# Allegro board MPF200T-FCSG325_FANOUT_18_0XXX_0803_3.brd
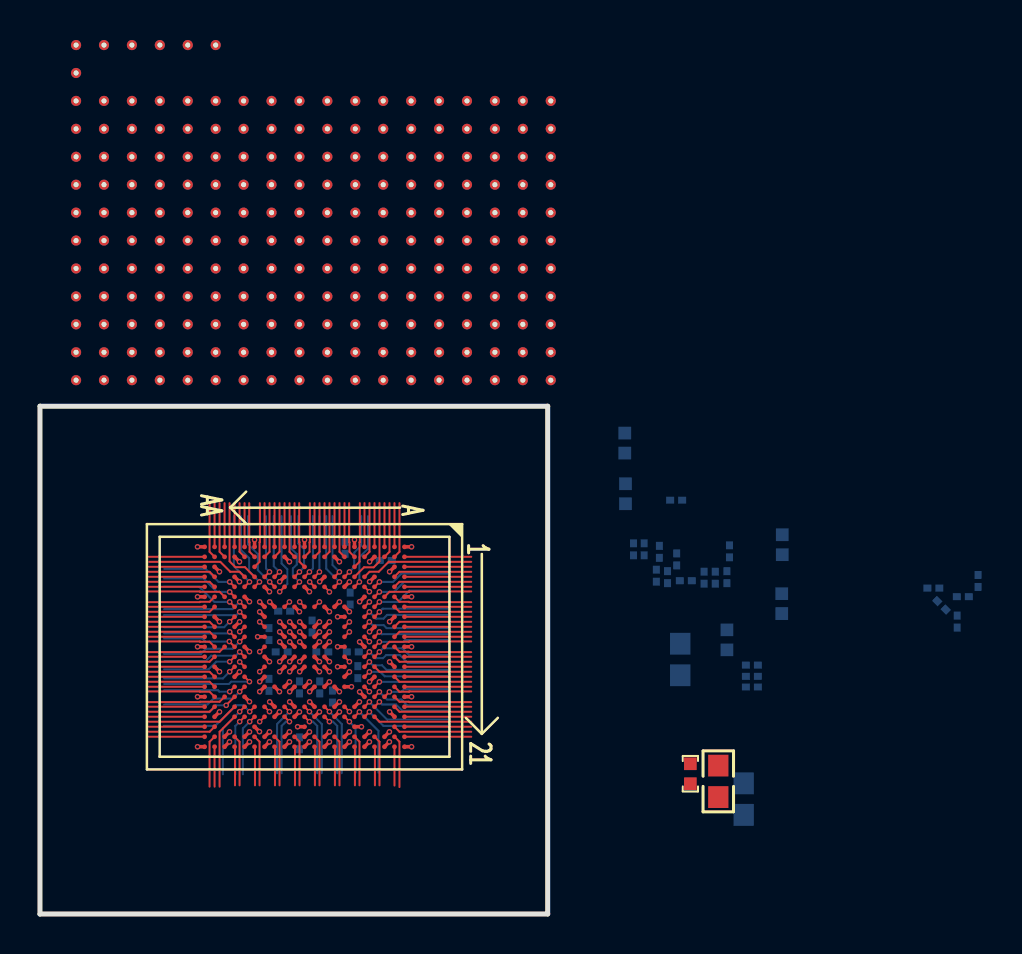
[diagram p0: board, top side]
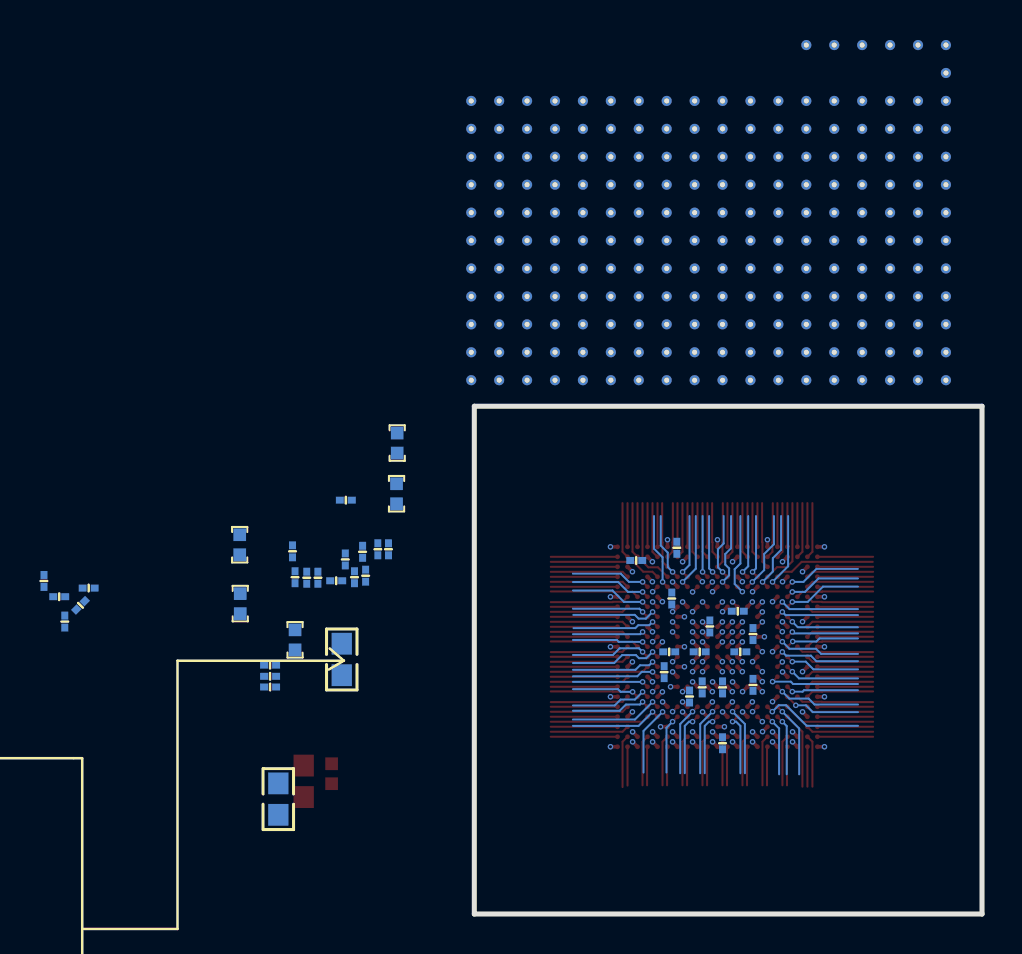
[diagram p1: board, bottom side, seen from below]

Outline 25.4 x 25.4 mm; copper layers: TOP, L2_GND1, L3_SIG1, L4_PWR, L5_GND2, BOTTOM. Coordinates in mm from the lower left corner of the outline.
Outline path: 0,25.4 0,0 25.4,0 25.4,25.4 0,25.4

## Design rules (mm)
net group DIFFPAIR0: nets N38034884 N38034886
net group DIFFPAIR1: nets N38034948 N38034950
net group DIFFPAIR2: nets N38034916 N38034918
net group XCVR_TX0: nets N38004278 N38004279
net group POWER: nets VDD

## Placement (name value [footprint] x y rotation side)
C33  0.01uF_16V  [BGA0201]  45.1 15.44 135 bottom
C34  0.1uF_16V  [BGA0201]  35.62 11.36 180 bottom
C36  0.1uF_16V  [BGA0201]  15.27 18.32 90 bottom
C37  0.01uF_16V  [BGA0201]  13.62 14.38 270 bottom
C38  0.1uF_16V  [BGA0201]  46.93 16.66 270 bottom
C40  0.1uF_16V  [BGA0201]  17.3 17.69 0 bottom
C41  0.1uF_16V  [BGA0201]  12.98 11.34 90 bottom
C42  0.1uF_16V  [BGA0201]  12.98 8.54 90 bottom
C45  0.1uF_16V  [BGA0201]  12.09 13.11 180 bottom
C46  0.1uF_16V  [BGA0201]  32.31 16.67 0 bottom
C49  0.1uF_16V_NL  [BGA0201]  14.63 10.88 270 bottom
C52  10uF_6.3V  [C0402]  37.11 15.53 270 bottom
C53  0.1uF_16V_NL  [BGA0201]  14 11.34 90 bottom
C55  10uF_6.3V  [C0402]  29.29 21.02 270 bottom
C56  0.1uF_16V_NL  [BGA0201]  45.89 14.63 270 bottom
C57  0.1uF_16V_NL  [BGA0201]  14.12 13.11 0 bottom
C60  4.7nF_16V  [BGA0201]  29.7 18.24 270 bottom
C62  4.7nF_16V  [BGA0201]  30.84 16.92 90 bottom
C66  4.7nF_16V  [BGA0201]  33.23 16.82 90 bottom
C71  0.01uF_16V  [BGA0201]  34.37 16.85 270 bottom
C76  0.1uF_16V  [BGA0201]  30.99 18.12 90 bottom
C78  47uF_4V  [C0603]  35.21 5.75 90 bottom
C79  0.1uF_16V  [BGA0201]  33.78 16.82 270 bottom
C80  0.1uF_16V  [BGA0201]  34.5 18.14 90 bottom
C82  0.1uF_16V  [BGA0201]  30.23 18.24 270 bottom
C83  0.1uF_16V  [BGA0201]  31.85 17.74 270 bottom
C84  0.1uF_16V  [BGA0201]  31.4 16.85 90 bottom
C85  10uF_6.3V  [C0402]  37.14 18.47 270 bottom
C86  0.1uF_16V  [BGA0201]  11.46 14 90 bottom
C88  0.1uF_16V  [BGA0201]  35.62 12.45 180 bottom
C95  47uF_4V  [C0603]  33.94 6.64 270 top
C96  10uF_6.3V  [C0402]  34.37 13.71 270 bottom
C103  0.1uF_16V  [BGA0201]  35.62 11.89 180 bottom
C104  0.1uF_16V  [BGA0201]  15.65 13.11 0 bottom
C105  0.1uF_16V  [BGA0201]  15.9 12.1 90 bottom
C106  0.1uF_16V  [BGA0201]  46.17 15.87 0 bottom
C107  0.1uF_16V  [BGA0201]  44.7 16.3 0 bottom
C108  0.1uF_16V  [BGA0201]  15.52 15.78 270 bottom
C110  0.1uF_16V  [BGA0201]  31.83 20.7 0 bottom
C111  0.1uF_16V  [BGA0201]  11.46 11.46 270 bottom
C112  0.1uF_16V  [BGA0201]  12.22 15.15 180 bottom
C113  10uF_6.3V  [C0402]  32.54 7.02 270 top
C115  4.7uF_10V  [C0402]  29.26 23.56 270 bottom
C1463  47uF_4V  [C0603]  32.03 12.73 90 bottom
NOREF  -  []  -0.13 3.15 0 top
NOREF#2  -  []  229.37 -121.61 0 top
TP1  -  [TP_VIA]  7.39 43.47 0 top
TP2  -  [TP_VIA]  8.79 43.47 0 top
TP16  -  [TP_VIA]  1.81 43.47 0 top
TP17  -  [TP_VIA]  3.2 43.47 0 top
TP18  -  [TP_VIA]  4.6 43.47 0 top
TP19  -  [TP_VIA]  6 43.47 0 top
TP20  -  [TP_VIA]  15.78 33.69 0 top
TP21  -  [TP_VIA]  6 35.09 0 top
TP22  -  [TP_VIA]  19.97 35.09 0 top
TP23  -  [TP_VIA]  21.36 35.09 0 top
TP24  -  [TP_VIA]  22.76 35.09 0 top
TP25  -  [TP_VIA]  24.16 35.09 0 top
TP26  -  [TP_VIA]  25.55 35.09 0 top
TP27  -  [TP_VIA]  1.81 36.48 0 top
TP28  -  [TP_VIA]  3.2 36.48 0 top
TP29  -  [TP_VIA]  4.6 36.48 0 top
TP30  -  [TP_VIA]  6 36.48 0 top
TP31  -  [TP_VIA]  7.39 36.48 0 top
TP32  -  [TP_VIA]  8.79 36.48 0 top
TP33  -  [TP_VIA]  10.19 36.48 0 top
TP34  -  [TP_VIA]  11.58 36.48 0 top
TP35  -  [TP_VIA]  12.98 36.48 0 top
TP36  -  [TP_VIA]  14.38 36.48 0 top
TP37  -  [TP_VIA]  15.78 36.48 0 top
TP38  -  [TP_VIA]  17.17 36.48 0 top
TP39  -  [TP_VIA]  18.57 36.48 0 top
TP40  -  [TP_VIA]  19.97 36.48 0 top
TP41  -  [TP_VIA]  21.36 36.48 0 top
TP42  -  [TP_VIA]  22.76 36.48 0 top
TP43  -  [TP_VIA]  24.16 36.48 0 top
TP44  -  [TP_VIA]  25.55 36.48 0 top
TP45  -  [TP_VIA]  1.81 37.88 0 top
TP46  -  [TP_VIA]  3.2 37.88 0 top
TP47  -  [TP_VIA]  4.6 37.88 0 top
TP48  -  [TP_VIA]  6 37.88 0 top
TP49  -  [TP_VIA]  7.39 37.88 0 top
TP50  -  [TP_VIA]  8.79 37.88 0 top
TP51  -  [TP_VIA]  10.19 37.88 0 top
TP52  -  [TP_VIA]  11.58 37.88 0 top
TP53  -  [TP_VIA]  12.98 37.88 0 top
TP54  -  [TP_VIA]  14.38 37.88 0 top
TP55  -  [TP_VIA]  15.78 37.88 0 top
TP56  -  [TP_VIA]  17.17 37.88 0 top
TP57  -  [TP_VIA]  18.57 37.88 0 top
TP58  -  [TP_VIA]  19.97 37.88 0 top
TP59  -  [TP_VIA]  21.36 37.88 0 top
TP60  -  [TP_VIA]  22.76 37.88 0 top
TP61  -  [TP_VIA]  24.16 37.88 0 top
TP62  -  [TP_VIA]  25.55 37.88 0 top
TP63  -  [TP_VIA]  1.81 39.28 0 top
TP64  -  [TP_VIA]  3.2 39.28 0 top
TP65  -  [TP_VIA]  4.6 39.28 0 top
TP66  -  [TP_VIA]  6 39.28 0 top
TP67  -  [TP_VIA]  7.39 39.28 0 top
TP68  -  [TP_VIA]  8.79 39.28 0 top
TP69  -  [TP_VIA]  10.19 39.28 0 top
TP70  -  [TP_VIA]  11.58 39.28 0 top
TP71  -  [TP_VIA]  12.98 39.28 0 top
TP72  -  [TP_VIA]  14.38 39.28 0 top
TP73  -  [TP_VIA]  15.78 39.28 0 top
TP74  -  [TP_VIA]  17.17 39.28 0 top
TP75  -  [TP_VIA]  18.57 39.28 0 top
TP76  -  [TP_VIA]  19.97 39.28 0 top
TP77  -  [TP_VIA]  21.36 39.28 0 top
TP78  -  [TP_VIA]  22.76 39.28 0 top
TP79  -  [TP_VIA]  24.16 39.28 0 top
TP80  -  [TP_VIA]  25.55 39.28 0 top
TP81  -  [TP_VIA]  1.81 40.67 0 top
TP82  -  [TP_VIA]  3.2 40.67 0 top
TP83  -  [TP_VIA]  4.6 40.67 0 top
TP84  -  [TP_VIA]  6 40.67 0 top
TP85  -  [TP_VIA]  7.39 40.67 0 top
TP86  -  [TP_VIA]  8.79 40.67 0 top
TP87  -  [TP_VIA]  10.19 40.67 0 top
TP88  -  [TP_VIA]  11.58 40.67 0 top
TP89  -  [TP_VIA]  12.98 40.67 0 top
TP90  -  [TP_VIA]  14.38 40.67 0 top
TP91  -  [TP_VIA]  15.78 40.67 0 top
TP92  -  [TP_VIA]  17.17 40.67 0 top
TP93  -  [TP_VIA]  18.57 40.67 0 top
TP94  -  [TP_VIA]  19.97 40.67 0 top
TP95  -  [TP_VIA]  21.36 40.67 0 top
TP96  -  [TP_VIA]  22.76 40.67 0 top
TP97  -  [TP_VIA]  24.16 40.67 0 top
TP98  -  [TP_VIA]  25.55 40.67 0 top
TP99  -  [TP_VIA]  1.81 42.07 0 top
TP100  -  [TP_VIA]  1.81 26.7 0 top
TP101  -  [TP_VIA]  3.2 26.7 0 top
TP102  -  [TP_VIA]  4.6 26.7 0 top
TP103  -  [TP_VIA]  6 26.7 0 top
TP104  -  [TP_VIA]  7.39 26.7 0 top
TP105  -  [TP_VIA]  8.79 26.7 0 top
TP106  -  [TP_VIA]  10.19 26.7 0 top
TP107  -  [TP_VIA]  11.58 26.7 0 top
TP108  -  [TP_VIA]  12.98 26.7 0 top
TP109  -  [TP_VIA]  14.38 26.7 0 top
TP110  -  [TP_VIA]  15.78 26.7 0 top
TP111  -  [TP_VIA]  17.17 26.7 0 top
TP112  -  [TP_VIA]  18.57 26.7 0 top
TP113  -  [TP_VIA]  19.97 26.7 0 top
TP114  -  [TP_VIA]  21.36 26.7 0 top
TP115  -  [TP_VIA]  22.76 26.7 0 top
TP116  -  [TP_VIA]  24.16 26.7 0 top
TP117  -  [TP_VIA]  25.55 26.7 0 top
TP118  -  [TP_VIA]  1.81 28.1 0 top
TP119  -  [TP_VIA]  3.2 28.1 0 top
TP120  -  [TP_VIA]  4.6 28.1 0 top
TP121  -  [TP_VIA]  6 28.1 0 top
TP122  -  [TP_VIA]  7.39 28.1 0 top
TP123  -  [TP_VIA]  8.79 28.1 0 top
TP124  -  [TP_VIA]  10.19 28.1 0 top
TP125  -  [TP_VIA]  11.58 28.1 0 top
TP126  -  [TP_VIA]  12.98 28.1 0 top
TP127  -  [TP_VIA]  14.38 28.1 0 top
TP128  -  [TP_VIA]  15.78 28.1 0 top
TP129  -  [TP_VIA]  17.17 28.1 0 top
TP130  -  [TP_VIA]  18.57 28.1 0 top
TP131  -  [TP_VIA]  19.97 28.1 0 top
TP132  -  [TP_VIA]  21.36 28.1 0 top
TP133  -  [TP_VIA]  22.76 28.1 0 top
TP134  -  [TP_VIA]  24.16 28.1 0 top
TP135  -  [TP_VIA]  25.55 28.1 0 top
TP136  -  [TP_VIA]  1.81 29.5 0 top
TP137  -  [TP_VIA]  3.2 29.5 0 top
TP138  -  [TP_VIA]  4.6 29.5 0 top
TP139  -  [TP_VIA]  6 29.5 0 top
TP140  -  [TP_VIA]  7.39 29.5 0 top
TP141  -  [TP_VIA]  8.79 29.5 0 top
TP142  -  [TP_VIA]  10.19 29.5 0 top
TP143  -  [TP_VIA]  11.58 29.5 0 top
TP144  -  [TP_VIA]  12.98 29.5 0 top
TP145  -  [TP_VIA]  14.38 29.5 0 top
TP146  -  [TP_VIA]  15.78 29.5 0 top
TP147  -  [TP_VIA]  17.17 29.5 0 top
TP148  -  [TP_VIA]  18.57 29.5 0 top
TP149  -  [TP_VIA]  19.97 29.5 0 top
TP150  -  [TP_VIA]  21.36 29.5 0 top
TP151  -  [TP_VIA]  22.76 29.5 0 top
TP152  -  [TP_VIA]  24.16 29.5 0 top
TP153  -  [TP_VIA]  25.55 29.5 0 top
TP154  -  [TP_VIA]  1.81 30.89 0 top
TP155  -  [TP_VIA]  3.2 30.89 0 top
TP156  -  [TP_VIA]  4.6 30.89 0 top
TP157  -  [TP_VIA]  6 30.89 0 top
TP158  -  [TP_VIA]  7.39 30.89 0 top
TP159  -  [TP_VIA]  8.79 30.89 0 top
TP160  -  [TP_VIA]  10.19 30.89 0 top
TP161  -  [TP_VIA]  11.58 30.89 0 top
TP162  -  [TP_VIA]  12.98 30.89 0 top
TP163  -  [TP_VIA]  14.38 30.89 0 top
TP164  -  [TP_VIA]  15.78 30.89 0 top
TP165  -  [TP_VIA]  17.17 30.89 0 top
TP166  -  [TP_VIA]  18.57 30.89 0 top
TP167  -  [TP_VIA]  19.97 30.89 0 top
TP168  -  [TP_VIA]  21.36 30.89 0 top
TP169  -  [TP_VIA]  22.76 30.89 0 top
TP170  -  [TP_VIA]  24.16 30.89 0 top
TP171  -  [TP_VIA]  25.55 30.89 0 top
TP172  -  [TP_VIA]  1.81 32.29 0 top
TP173  -  [TP_VIA]  3.2 32.29 0 top
TP174  -  [TP_VIA]  4.6 32.29 0 top
TP175  -  [TP_VIA]  6 32.29 0 top
TP176  -  [TP_VIA]  7.39 32.29 0 top
TP177  -  [TP_VIA]  8.79 32.29 0 top
TP178  -  [TP_VIA]  10.19 32.29 0 top
TP179  -  [TP_VIA]  11.58 32.29 0 top
TP180  -  [TP_VIA]  12.98 32.29 0 top
TP181  -  [TP_VIA]  14.38 32.29 0 top
TP182  -  [TP_VIA]  15.78 32.29 0 top
TP183  -  [TP_VIA]  17.17 32.29 0 top
TP184  -  [TP_VIA]  18.57 32.29 0 top
TP185  -  [TP_VIA]  19.97 32.29 0 top
TP186  -  [TP_VIA]  21.36 32.29 0 top
TP187  -  [TP_VIA]  22.76 32.29 0 top
TP188  -  [TP_VIA]  24.16 32.29 0 top
TP189  -  [TP_VIA]  25.55 32.29 0 top
TP190  -  [TP_VIA]  1.81 33.69 0 top
TP191  -  [TP_VIA]  3.2 33.69 0 top
TP192  -  [TP_VIA]  4.6 33.69 0 top
TP193  -  [TP_VIA]  6 33.69 0 top
TP194  -  [TP_VIA]  7.39 33.69 0 top
TP195  -  [TP_VIA]  8.79 33.69 0 top
TP196  -  [TP_VIA]  10.19 33.69 0 top
TP197  -  [TP_VIA]  11.58 33.69 0 top
TP198  -  [TP_VIA]  12.98 33.69 0 top
TP199  -  [TP_VIA]  14.38 33.69 0 top
TP200  -  [TP_VIA]  17.17 33.69 0 top
TP201  -  [TP_VIA]  18.57 33.69 0 top
TP202  -  [TP_VIA]  19.97 33.69 0 top
TP203  -  [TP_VIA]  21.36 33.69 0 top
TP204  -  [TP_VIA]  22.76 33.69 0 top
TP205  -  [TP_VIA]  24.16 33.69 0 top
TP206  -  [TP_VIA]  25.55 33.69 0 top
TP207  -  [TP_VIA]  1.81 35.09 0 top
TP208  -  [TP_VIA]  3.2 35.09 0 top
TP209  -  [TP_VIA]  4.6 35.09 0 top
TP210  -  [TP_VIA]  7.39 35.09 0 top
TP211  -  [TP_VIA]  8.79 35.09 0 top
TP212  -  [TP_VIA]  10.19 35.09 0 top
TP213  -  [TP_VIA]  11.58 35.09 0 top
TP214  -  [TP_VIA]  12.98 35.09 0 top
TP215  -  [TP_VIA]  14.38 35.09 0 top
TP216  -  [TP_VIA]  15.78 35.09 0 top
TP217  -  [TP_VIA]  17.17 35.09 0 top
TP218  -  [TP_VIA]  18.57 35.09 0 top
U1  -  [MPF200T-FCSG325]  13.24 13.37 270 top

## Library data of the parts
C33 C34 C36-C38 C40-C42 C45 C46 C49 C52 C53 C55-C57 C60 C62 C66 C71 C76 C78-C80 C82-C86 C88 C95 C96 C103-C108 C110-C113 C115 C1463 = CAPACITOR NON-POL
TP1 TP2 TP16-TP218 = T POINT A
U1 = MPF200T-FCSG325

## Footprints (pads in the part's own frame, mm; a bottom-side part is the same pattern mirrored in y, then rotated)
BGA0201
  rect 0.399x0.351 smd: 1(-0.3,0) 2(0.3,0)
C0402
  rect 0.635x0.635 smd: 1(-0.5,0) 2(0.5,0)
C0603
  rect 1.092x1.016 smd: 1(-0.787,0) 2(0.787,0)
MPF200T-FCSG325
  round 0.24 smd: A1(-5,5) A2(-4.5,5) A3(-4,5) A4(-3.5,5) A5(-3,5) A6(-2.5,5) A7(-2,5) A8(-1.5,5) A9(-1,5) A10(-0.5,5) A11(0,5) A12(0.5,5) A13(1,5) A14(1.5,5) A15(2,5) A16(2.5,5) A17(3,5) A18(3.5,5) A19(4,5) A20(4.5,5) A21(5,5) AA1(-5,-5) AA2(-4.5,-5) AA3(-4,-5) AA4(-3.5,-5) AA5(-3,-5) AA6(-2.5,-5) AA7(-2,-5) AA8(-1.5,-5) AA9(-1,-5) AA10(-0.5,-5) AA11(0,-5) AA12(0.5,-5) AA13(1,-5) AA14(1.5,-5) AA15(2,-5) AA16(2.5,-5) AA17(3,-5) AA18(3.5,-5) AA19(4,-5) AA20(4.5,-5) AA21(5,-5) B1(-5,4.5) B2(-4.5,4.5) B3(-4,4.5) B4(-3.5,4.5) B5(-3,4.5) B6(-2.5,4.5) B7(-2,4.5) B8(-1.5,4.5) B9(-1,4.5) B10(-0.5,4.5) B11(0,4.5) B12(0.5,4.5) B13(1,4.5) B14(1.5,4.5) B15(2,4.5) B16(2.5,4.5) B17(3,4.5) B18(3.5,4.5) B19(4,4.5) B20(4.5,4.5) B21(5,4.5) C1(-5,4) C2(-4.5,4) C6(-2.5,4) C11(0,4) C16(2.5,4) C20(4.5,4) C21(5,4) D1(-5,3.5) D2(-4.5,3.5) D4(-3.5,3.5) D5(-3,3.5) D6(-2.5,3.5) D7(-2,3.5) D8(-1.5,3.5) D9(-1,3.5) D10(-0.5,3.5) D11(0,3.5) D12(0.5,3.5) D13(1,3.5) D14(1.5,3.5) D15(2,3.5) D16(2.5,3.5) D17(3,3.5) D18(3.5,3.5) D20(4.5,3.5) D21(5,3.5) E1(-5,3) E2(-4.5,3) E4(-3.5,3) E5(-3,3) E6(-2.5,3) E7(-2,3) E8(-1.5,3) E9(-1,3) E10(-0.5,3) E11(0,3) E12(0.5,3) E13(1,3) E14(1.5,3) E15(2,3) E16(2.5,3) E17(3,3) E18(3.5,3) E20(4.5,3) E21(5,3) F1(-5,2.5) F2(-4.5,2.5) F3(-4,2.5) F4(-3.5,2.5) F5(-3,2.5) F17(3,2.5) F18(3.5,2.5) F19(4,2.5) F20(4.5,2.5) F21(5,2.5) G1(-5,2) G2(-4.5,2) G4(-3.5,2) G5(-3,2) G7(-2,2) G8(-1.5,2) G9(-1,2) G10(-0.5,2) G11(0,2) G12(0.5,2) G13(1,2) G14(1.5,2) G15(2,2) G17(3,2) G18(3.5,2) G20(4.5,2) G21(5,2) H1(-5,1.5) H2(-4.5,1.5) H4(-3.5,1.5) H5(-3,1.5) H7(-2,1.5) H15(2,1.5) H17(3,1.5) H18(3.5,1.5) H20(4.5,1.5) H21(5,1.5) J1(-5,1) J2(-4.5,1) J4(-3.5,1) J5(-3,1) J7(-2,1) J9(-1,1) J10(-0.5,1) J11(0,1) J12(0.5,1) J13(1,1) J15(2,1) J17(3,1) J18(3.5,1) J20(4.5,1) J21(5,1) K1(-5,0.5) K2(-4.5,0.5) K4(-3.5,0.5) K5(-3,0.5) K7(-2,0.5) K9(-1,0.5) K10(-0.5,0.5) K11(0,0.5) K12(0.5,0.5) K13(1,0.5) K15(2,0.5) K17(3,0.5) K18(3.5,0.5) K20(4.5,0.5) K21(5,0.5) L1(-5,0) L2(-4.5,0) L3(-4,0) L4(-3.5,0) L5(-3,0) L7(-2,0) L9(-1,0) L10(-0.5,0) L11(0,0) L12(0.5,0) L13(1,0) L15(2,0) L17(3,0) L18(3.5,0) L19(4,0) L20(4.5,0) L21(5,0) M1(-5,-0.5) M2(-4.5,-0.5) M4(-3.5,-0.5) M5(-3,-0.5) M7(-2,-0.5) M9(-1,-0.5) M10(-0.5,-0.5) M11(0,-0.5) M12(0.5,-0.5) M13(1,-0.5) M15(2,-0.5) M17(3,-0.5) M18(3.5,-0.5) M20(4.5,-0.5) M21(5,-0.5) N1(-5,-1) N2(-4.5,-1) N4(-3.5,-1) N5(-3,-1) N7(-2,-1) N9(-1,-1) N10(-0.5,-1) N11(0,-1) N12(0.5,-1) N13(1,-1) N15(2,-1) N17(3,-1) N18(3.5,-1) N20(4.5,-1) N21(5,-1) P1(-5,-1.5) P2(-4.5,-1.5) P4(-3.5,-1.5) P5(-3,-1.5) P7(-2,-1.5) P15(2,-1.5) P17(3,-1.5) P18(3.5,-1.5) P20(4.5,-1.5) P21(5,-1.5) R1(-5,-2) R2(-4.5,-2) R4(-3.5,-2) R5(-3,-2) R7(-2,-2) R8(-1.5,-2) R9(-1,-2) R10(-0.5,-2) R11(0,-2) R12(0.5,-2) R13(1,-2) R14(1.5,-2) R15(2,-2) R17(3,-2) R18(3.5,-2) R20(4.5,-2) R21(5,-2) T1(-5,-2.5) T2(-4.5,-2.5) T3(-4,-2.5) T4(-3.5,-2.5) T5(-3,-2.5) T17(3,-2.5) T18(3.5,-2.5) T19(4,-2.5) T20(4.5,-2.5) T21(5,-2.5) U1(-5,-3) U2(-4.5,-3) U4(-3.5,-3) U5(-3,-3) U6(-2.5,-3) U7(-2,-3) U8(-1.5,-3) U9(-1,-3) U10(-0.5,-3) U11(0,-3) U12(0.5,-3) U13(1,-3) U14(1.5,-3) U15(2,-3) U16(2.5,-3) U17(3,-3) U18(3.5,-3) U20(4.5,-3) U21(5,-3) V1(-5,-3.5) V2(-4.5,-3.5) V4(-3.5,-3.5) V5(-3,-3.5) V6(-2.5,-3.5) V7(-2,-3.5) V8(-1.5,-3.5) V9(-1,-3.5) V10(-0.5,-3.5) V11(0,-3.5) V12(0.5,-3.5) V13(1,-3.5) V14(1.5,-3.5) V15(2,-3.5) V16(2.5,-3.5) V17(3,-3.5) V18(3.5,-3.5) V20(4.5,-3.5) V21(5,-3.5) W1(-5,-4) W2(-4.5,-4) W6(-2.5,-4) W11(0,-4) W16(2.5,-4) W20(4.5,-4) W21(5,-4) Y1(-5,-4.5) Y2(-4.5,-4.5) Y3(-4,-4.5) Y4(-3.5,-4.5) Y5(-3,-4.5) Y6(-2.5,-4.5) Y7(-2,-4.5) Y8(-1.5,-4.5) Y9(-1,-4.5) Y10(-0.5,-4.5) Y11(0,-4.5) Y12(0.5,-4.5) Y13(1,-4.5) Y14(1.5,-4.5) Y15(2,-4.5) Y16(2.5,-4.5) Y17(3,-4.5) Y18(3.5,-4.5) Y19(4,-4.5) Y20(4.5,-4.5) Y21(5,-4.5)
TP_VIA
  round 0.508 hole 0.254: 1(0,0)

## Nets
GND: C33.2 C34.2 C36.2 C37.2 C38.2 C40.2 C41.2 C42.1 C45.2 C46.1 C49.2 C52.1 C53.2 C55.1 C56.2 C57.2 C60.1 C62.1 C66.1 C71.2 C76.2 C78.1 C79.2 C80.2 C82.1 C83.1 C84.1 C85.1 C86.2 C88.2 C95.1 C96.1 C103.2 C104.2 C105.2 C106.1 C107.2 C108.1 C110.2 C111.1 C112.2 C113.1 C115.1 C1463.1 U1.A1(VSS_19) U1.A6(VSS_23) U1.A11(VSS_20) U1.A16(VSS_21) U1.A21(VSS_22) U1.AA1(VSS_24) U1.AA6(VSS_29) U1.AA11(VSS_25) U1.AA16(VSS_26) U1.AA21(VSS_28) U1.C20(VSS_1) U1.C21(VSS_2) U1.D4(VSS_31) U1.D9(VSS_32) U1.D14(VSS_30) U1.E21(VSS_3) U1.F1(VSS_33) U1.G14(VSS_34) U1.G21(VSS_4) U1.H7(VSS_35) U1.H17(VSS_5) U1.H18(VSS_6) U1.J4(VSS_39) U1.J9(VSS_40) U1.J11(VSS_36) U1.J13(VSS_37) U1.J15(VSS_38) U1.J21(VSS_7) U1.K10(VSS_41) U1.K12(VSS_42) U1.K18(VSS_8) U1.L1(VSS_43) U1.L9(VSS_47) U1.L11(VSS_44) U1.L13(VSS_45) U1.L15(VSS_46) U1.L21(VSS_9) U1.M10(VSS_48) U1.M12(VSS_49) U1.M18(VSS_10) U1.N4(VSS_53) U1.N9(VSS_54) U1.N11(VSS_50) U1.N13(VSS_51) U1.N15(VSS_52) U1.N21(VSS_11) U1.P17(VSS_12) U1.P18(VSS_13) U1.R8(VSS_55) U1.R21(VSS_14) U1.T1(VSS_56) U1.T19(VSS_15) U1.U21(VSS_16) U1.V4(VSS_58) U1.V9(VSS_SN) U1.V14(VSS_57) U1.W20(VSS_17) U1.W21(VSS_18)
VDD: C33.1 C37.1 C41.1 C45.1 C49.1 C53.1 C56.1 C57.1 C78.2 C1463.2 U1.H15(VDD_1) U1.J12(VDD_2) U1.K9(VDD_6) U1.K11(VDD_3) U1.K13(VDD_4) U1.K15(VDD_5) U1.L10(VDD_7) U1.L12(VDD_8) U1.M11(VDD_9) U1.M13(VDD_10) U1.M15(VDD_11) U1.N10(VDD_12) U1.N12(VDD_SP)
VDD18: C86.1 C88.1 C95.2 C96.2 U1.P7(VDD18_2) U1.P15(VDD18_1) U1.R10(VDD18_3) U1.R14(VDD18_4)
VDD25: C103.1 C105.1 C107.1 C108.2 C111.2 C113.2 U1.G7(VDD25_2) U1.G15(VDD25_1) U1.M9(VDD25_3) U1.R7(VDD25_5) U1.R15(VDD25_4)
VDD_XCVR_CLK: U1.K17(VDD_XCVR_CLK_1) U1.M17(VDD_XCVR_CLK_2)
VDDA: C60.2 C62.2 C66.2 C71.1 C76.1 C79.1 C80.1 C82.2 C83.2 C84.2 C85.2 U1.G20(VDDA_1) U1.J20(VDDA_2) U1.N20(VDDA_3) U1.R20(VDDA_4) U1.U20(VDDA_5)
VDDA25: C34.1 C38.1 C42.2 C46.2 C52.2 U1.L19(VDDA25_1) U1.L20(VDDA25_2)
VDDAUX2: U1.E6(VDDAUX2_1) U1.F17(VDDAUX2_2) U1.G8(VDDAUX2_4) U1.G13(VDDAUX2_3)
VDDAUX4: C110.1 C112.1 C115.2 U1.J7(VDDAUX4_1) U1.M7(VDDAUX4_2)
VDDI0: U1.N2(VDDI0_1) U1.R5(VDDI0_2) U1.U6(VDDI0_3) U1.V2(VDDI0_4) U1.Y3(VDDI0_5)
VDDI1: U1.R12(VDDI1_1) U1.U11(VDDI1_2) U1.U16(VDDI1_3) U1.Y8(VDDI1_6) U1.Y13(VDDI1_4) U1.Y18(VDDI1_5)
VDDI2: U1.B3(VDDI2_3) U1.B8(VDDI2_4) U1.B13(VDDI2_1) U1.B18(VDDI2_2) U1.E11(VDDI2_5) U1.E16(VDDI2_6)
VDDI3: C104.1 C106.2 U1.G11(VDDI3_1) U1.J10(VDDI3_2)
VDDI4: C36.1 C40.1 C55.2 U1.D2(VDDI4_1) U1.G5(VDDI4_2) U1.H2(VDDI4_3) U1.L5(VDDI4_4)
XCVR_VREF: U1.E20(XCVR_VREF_1) U1.F19(XCVR_VREF_2)
N38004278: TP18.1(TP) U1.D21(XCVR_0_TX0_P)
N38004279: TP19.1(TP) U1.D20(XCVR_0_TX0_N)
N38004284: TP1.1(TP) U1.F21(XCVR_0_RX0_P)
N38004285: TP2.1(TP) U1.F20(XCVR_0_RX0_N)
N38032541: TP16.1(TP) U1.M1(GPIO108NB4_DDR_W_11)
N38032543: TP17.1(TP) U1.N1(GPIO108PB4/CLKIN_W_7/CCC_NW_CLK)
N38032613: TP20.1(TP) U1.M2(GPIO109PB4/DQS_DDR_W_11)
N38032615: TP21.1(TP) U1.L2(GPIO109NB4/DQS_DDR_W_11)
N38032633: TP22.1(TP) U1.M4(GPIO114PB4/CLKIN_W_6/CCC_NW_CLK)
N38032635: TP23.1(TP) U1.L3(GPIO114NB4_DDR_W_10)
N38032653: TP25.1(TP) U1.N5(GPIO115PB4/DQS/CCC_NW_PLL0_OUT0)
N38032655: TP24.1(TP) U1.M5(GPIO115NB4/DQS_DDR_W_10)
N38032673: TP26.1(TP) U1.K2(GPIO142PB4_DDR_W_5)
N38032675: TP27.1(TP) U1.K1(GPIO142NB4_DDR_W_5)
N38032693: TP29.1(TP) U1.H1(GPIO144PB4_DDR_W_5)
N38032695: TP28.1(TP) U1.J1(GPIO144NB4_DDR_W_5)
N38032713: TP31.1(TP) U1.L4(GPIO145PB4/DQS_DDR_W_5)
N38032715: TP30.1(TP) U1.K4(GPIO145NB4/DQS_DDR_W_5)
N38032733: TP32.1(TP) U1.H4(GPIO148PB4_DDR_W_4)
N38032735: TP33.1(TP) U1.J2(GPIO148NB4_DDR_W_4)
N38032753: TP35.1(TP) U1.H5(GPIO149PB4/CLKIN_W_5/CCC_NW_CLK)
N38032755: TP34.1(TP) U1.G4(GPIO149NB4_DDR_W_4)
N38032773: TP36.1(TP) U1.K7(GPIO150PB4/CLKIN_W_4/CCC_NW_CLK)
N38032775: TP37.1(TP) U1.L7(GPIO150NB4_DDR_W_4)
N38032793: TP38.1(TP) U1.G2(GPIO151PB4/DQS_DDR_W_4)
N38032795: TP39.1(TP) U1.G1(GPIO151NB4/DQS_DDR_W_4)
N38032813: TP41.1(TP) U1.F4(GPIO152PB4_DDR_W_4)
N38032815: TP40.1(TP) U1.F3(GPIO152NB4_DDR_W_4)
N38032833: TP42.1(TP) U1.J5(GPIO153PB4/CLKIN_W_3/CCC_SW_CLK)
N38032835: TP43.1(TP) U1.K5(GPIO153NB4_DDR_W_4)
N38032879: TP44.1(TP) U1.B1(GPIO175NB5/DQS_DDR_W_0)
N38032881: TP45.1(TP) U1.C1(GPIO175PB5/DQS/CCC_SW_PLL0_OUT0)
N38032909: TP46.1(TP) U1.C2(GPIO176NB5_DDR_W_0)
N38032911: TP47.1(TP) U1.B2(GPIO176PB5_DDR_W_0)
N38032919: TP49.1(TP) U1.E5(GPIO177NB5_DDR_W_0)
N38032935: TP48.1(TP) U1.D5(GPIO177PB5/CLKIN_W_0/CCC_SW_CLK)
N38033008: TP50.1(TP) U1.F2(GPIO172NB5_DDR_W_0)
N38033016: TP51.1(TP) U1.E2(GPIO172PB5/CCC_SW_PLL0_OUT1_DDR)
N38033024: TP52.1(TP) U1.E1(GPIO173NB5_DDR_W_0)
N38033026: TP53.1(TP) U1.D1(GPIO173PB5/CLKIN_W_2/CCC_SW_CLK)
N38033040: TP55.1(TP) U1.F5(GPIO174NB5_DDR_W_0)
N38033048: TP54.1(TP) U1.E4(GPIO174PB5/CLKIN_W_1/CCC_SW_CLK)
N38033820: TP56.1(TP) U1.D11(GPIO12PB2/CLKIN_S_4_DDR_S_3)
N38033822: TP57.1(TP) U1.D12(GPIO12NB2_DDR_S_3)
N38033842: TP58.1(TP) U1.B11(GPIO13NB2_DDR_S_3)
N38033844: TP59.1(TP) U1.C11(GPIO13PB2/CLKIN_S_5_DDR_S_3)
N38033852: TP60.1(TP) U1.E12(GPIO14NB2/DQS_DDR_S_3)
N38033854: TP61.1(TP) U1.G12(GPIO14PB2/DQS_DDR_S_3)
N38033868: TP63.1(TP) U1.B12(GPIO15NB2_DDR_S_3)
N38033870: TP62.1(TP) U1.A12(GPIO15PB2/CLKIN_S_6_DDR_S_3)
N38033896: TP64.1(TP) U1.D13(GPIO16NB2/LPRB_B_DDR_S_3)
N38033898: TP65.1(TP) U1.E13(GPIO16PB2/LPRB_A_DDR_S_3)
N38033906: TP67.1(TP) U1.A14(GPIO17NB2_DDR_S_3)
N38033908: TP66.1(TP) U1.A13(GPIO17PB2/CLKIN_S_7_DDR_S_3)
N38033916: TP68.1(TP) U1.E15(GPIO30NB2_DDR_S_6)
N38033918: TP69.1(TP) U1.E14(GPIO30PB2_DDR_S_6)
N38033932: TP70.1(TP) U1.A15(GPIO31NB2_DDR_S_6)
N38033934: TP71.1(TP) U1.B14(GPIO31PB2_DDR_S_6)
N38033960: TP73.1(TP) U1.D17(GPIO32NB2/DQS_DDR_S_6)
N38033962: TP72.1(TP) U1.D16(GPIO32PB2/DQS/CCC_SE_PLL0_OUT0_)
N38033970: TP74.1(TP) U1.B15(GPIO33NB2_DDR_S_6)
N38033972: TP75.1(TP) U1.B16(GPIO33PB2/CLKIN_S_8/CCC_SE_CLKI)
N38033980: TP76.1(TP) U1.B17(GPIO34NB2_DDR_S_6)
N38033982: TP77.1(TP) U1.A17(GPIO34PB2/CCC_SE_PLL0_OUT1_DDR_)
N38033996: TP78.1(TP) U1.C16(GPIO35NB2_DDR_S_6)
N38033998: TP79.1(TP) U1.D15(GPIO35PB2/CLKIN_S_9/CCC_SE_CLKI)
N38034024: TP81.1(TP) U1.F18(GPIO36NB2_DDR_S_7)
N38034026: TP80.1(TP) U1.E18(GPIO36PB2_DDR_S_7)
N38034392: TP83.1(TP) U1.D18(GPIO37NB2_DDR_S_7)
N38034394: TP82.1(TP) U1.E17(GPIO37PB2_DDR_S_7)
N38034396: TP84.1(TP) U1.A19(GPIO38NB2/DQS_DDR_S_7)
N38034398: TP85.1(TP) U1.A18(GPIO38PB2/DQS/CCC_SE_PLL1_OUT0_)
N38034406: TP87.1(TP) U1.G18(GPIO39NB2_DDR_S_7)
N38034408: TP88.1(TP) U1.G17(GPIO39PB2/CCC_SE_CLKIN_S_10/CCC)
N38034440: TP90.1(TP) U1.B19(GPIO40NB2_DDR_S_7)
N38034442: TP86.1(TP) U1.A20(GPIO40PB2/CCC_SE_PLL1_OUT1_DDR_)
N38034456: TP89.1(TP) U1.B20(GPIO41NB2_DDR_S_7)
N38034458: TP91.1(TP) U1.B21(GPIO41PB2/CCC_SE_CLKIN_S_11_DDR)
N38034460: TP92.1(TP) U1.D7(GPIO178NB2_DDR_S_0)
N38034462: TP93.1(TP) U1.E7(GPIO178PB2/CCC_SW_CLKIN_S_0_DDR)
N38034470: TP95.1(TP) U1.A3(GPIO179NB2_DDR_S_0)
N38034472: TP96.1(TP) U1.A2(GPIO179PB2/CCC_SW_CLKIN_S_1_DDR)
N38034504: TP97.1(TP) U1.A4(GPIO180NB2/DQS_DDR_S_0)
N38034506: TP94.1(TP) U1.B4(GPIO180PB2/DQS/CCC_SW_PLL1_OUT0)
N38034582: TP98.1(TP) U1.D6(GPIO181PB2/CLKIN_S_2/CCC_SW_CLK)
N38034584: TP99.1(TP) U1.C6(GPIO181NB2_DDR_S_0)
N38034604: TP100.1(TP) U1.A5(GPIO182NB2_DDR_S_0)
N38034606: TP101.1(TP) U1.B5(GPIO182PB2/CCC_SW_PLL1_OUT1_DDR)
N38034614: TP102.1(TP) U1.B7(GPIO183NB2_DDR_S_0)
N38034616: TP103.1(TP) U1.B6(GPIO183PB2/CLKIN_S_3/CCC_SW_CLK)
N38034678: TP104.1(TP) U1.K20(XCVR_0_TX1_P)
N38034680: TP105.1(TP) U1.K21(XCVR_0_TX1_N)
N38034762: TP106.1(TP) U1.M21(XCVR_0_TX2_N)
N38034764: TP107.1(TP) U1.M20(XCVR_0_TX2_P)
N38034852: TP108.1(TP) U1.V20(XCVR_0_TX3_N)
N38034854: TP109.1(TP) U1.V21(XCVR_0_TX3_P)
N38034884: TP110.1(TP) U1.L18(XCVR_0A_REFCLK_N)
N38034886: TP111.1(TP) U1.L17(XCVR_0A_REFCLK_P)
N38034916: TP112.1(TP) U1.N18(XCVR_0B_REFCLK_N)
N38034918: TP113.1(TP) U1.N17(XCVR_0B_REFCLK_P)
N38034948: TP114.1(TP) U1.J18(XCVR_0C_REFCLK_N)
N38034950: TP115.1(TP) U1.J17(XCVR_0C_REFCLK_P)
N38034992: TP116.1(TP) U1.H21(XCVR_0_RX1_N)
N38034994: TP117.1(TP) U1.H20(XCVR_0_RX1_P)
N38035012: TP119.1(TP) U1.P21(XCVR_0_RX2_N)
N38035014: TP118.1(TP) U1.P20(XCVR_0_RX2_P)
N38035032: TP121.1(TP) U1.T20(XCVR_0_RX3_N)
N38035034: TP120.1(TP) U1.T21(XCVR_0_RX3_P)
N38035064: TP122.1(TP) U1.A9(SC_IO_CFG_INTERFACE)
N38035090: TP123.1(TP) U1.B9(SC_EXIT_FLASH_FREEZE_B)
N38035106: TP124.1(TP) U1.A10(SC_SPI_ENABLE)
N38035116: TP125.1(TP) U1.G9(SC_SPI_SCK)
N38035126: TP126.1(TP) U1.B10(SC_SPI_SDI)
N38035136: TP127.1(TP) U1.A8(SC_SPI_SDO)
N38035146: TP128.1(TP) U1.A7(SC_SPI_SS)
N38035185: TP129.1(TP) U1.E10(DEVRST_N)
N38035201: TP130.1(TP) U1.D10(JTAG_TCK)
N38035211: TP131.1(TP) U1.E9(JTAG_TDI)
N38035221: TP132.1(TP) U1.E8(JTAG_TDO)
N38035231: TP133.1(TP) U1.D8(JTAG_TMS)
N38035241: TP134.1(TP) U1.G10(JTAG_TRSTB)
N38035401: TP135.1(TP) U1.AA14(HSIO54NB1_DDR_N_8)
N38035403: TP136.1(TP) U1.AA13(HSIO54PB1_DDR_N_8)
N38035423: TP137.1(TP) U1.V13(HSIO55PB1_DDR_N_8)
N38035425: TP138.1(TP) U1.Y14(HSIO55NB1_DDR_N_8)
N38035433: TP139.1(TP) U1.U13(HSIO56PB1_DDR_N_8)
N38035435: TP140.1(TP) U1.R13(HSIO56NB1_DDR_N_8)
N38035449: TP142.1(TP) U1.Y12(HSIO57PB1/DQS_DDR_N_8)
N38035451: TP141.1(TP) U1.AA12(HSIO57NB1/DQS_DDR_N_8)
N38035477: TP143.1(TP) U1.Y11(HSIO58PB1_DDR_N_8)
N38035479: TP144.1(TP) U1.W11(HSIO58NB1_DDR_N_8)
N38035487: TP146.1(TP) U1.U12(HSIO59PB1_DDR_N_8)
N38035489: TP145.1(TP) U1.R11(HSIO59NB1_DDR_N_8)
N38035497: TP147.1(TP) U1.AA10(HSIO66PB1/CLKIN_N_7_DDR_N_6)
N38035499: TP148.1(TP) U1.Y10(HSIO66NB1_DDR_N_6)
N38035513: TP149.1(TP) U1.AA9(HSIO67PB1_DDR_N_6)
N38035515: TP150.1(TP) U1.Y9(HSIO67NB1_DDR_N_6)
N38035541: TP152.1(TP) U1.V11(HSIO68PB1/CLKIN_N_6_DDR_N_6)
N38035543: TP151.1(TP) U1.V12(HSIO68NB1_DDR_N_6)
N38035551: TP153.1(TP) U1.AA8(HSIO69PB1/DQS_DDR_N_6)
N38035553: TP154.1(TP) U1.Y7(HSIO69NB1/DQS_DDR_N_6)
N38035561: TP155.1(TP) U1.AA7(HSIO70PB1_DDR_N_6)
N38035563: TP156.1(TP) U1.Y6(HSIO70NB1_DDR_N_6)
N38035577: TP157.1(TP) U1.V10(HSIO71PB1_DDR_N_6)
N38035579: TP158.1(TP) U1.U10(HSIO71NB1_DDR_N_6)
N38036549: TP161.1(TP) U1.AA20(HSIO42NB1_DDR_N_10)
N38036551: TP159.1(TP) U1.Y21(HSIO42PB1/CCC_NE_CLKIN_N_11_DDR)
N38036553: TP160.1(TP) U1.Y20(HSIO43PB1/CCC_NE_PLL0_OUT1_DDR_)
N38036573: TP162.1(TP) U1.Y19(HSIO43NB1_DDR_N_10)
N38036575: TP164.1(TP) U1.V18(HSIO44PB1/CCC_NE_CLKIN_N_10/CCC)
N38036577: TP163.1(TP) U1.U18(HSIO44NB1_DDR_N_10)
N38036585: TP165.1(TP) U1.R17(HSIO45PB1/DQS/CCC_NE_PLL0_OUT0_)
N38036587: TP167.1(TP) U1.R18(HSIO45NB1/DQS_DDR_N_10)
N38036619: TP166.1(TP) U1.T17(HSIO46PB1_DDR_N_10)
N38036621: TP169.1(TP) U1.T18(HSIO46NB1_DDR_N_10)
N38036623: TP170.1(TP) U1.U17(HSIO47PB1_DDR_N_10)
N38036637: TP168.1(TP) U1.V17(HSIO47NB1_DDR_N_10)
N38036639: TP171.1(TP) U1.AA19(HSIO48PB1/CLKIN_N_9/CCC_NE_CLKI)
N38036641: TP172.1(TP) U1.AA18(HSIO48NB1_DDR_N_9)
N38036649: TP174.1(TP) U1.V15(HSIO49PB1/CCC_NE_PLL1_OUT1_DDR_)
N38036651: TP175.1(TP) U1.V16(HSIO49NB1_DDR_N_9)
N38036683: TP177.1(TP) U1.AA17(HSIO50PB1/CLKIN_N_8/CCC_NE_CLKI)
N38036685: TP173.1(TP) U1.Y17(HSIO50NB1_DDR_N_9)
N38036687: TP176.1(TP) U1.U14(HSIO51PB1/DQS/CCC_NE_PLL1_OUT0_)
N38036701: TP178.1(TP) U1.U15(HSIO51NB1/DQS_DDR_N_9)
N38036703: TP179.1(TP) U1.Y16(HSIO52PB1_DDR_N_9)
N38036705: TP180.1(TP) U1.W16(HSIO52NB1_DDR_N_9)
N38036713: TP181.1(TP) U1.AA15(HSIO53PB1_DDR_N_9)
N38036715: TP182.1(TP) U1.Y15(HSIO53NB1_DDR_N_9)
N38037389: TP185.1(TP) U1.U1(HSIO102NB0-DDR_N_0)
N38037391: TP183.1(TP) U1.T2(HSIO102PB0/CLKIN_N_3/CCC_NW_CLK)
N38037393: TP184.1(TP) U1.R4(HSIO103PB0/CCC_NW_PLL1_OUT1-DDR)
N38037413: TP186.1(TP) U1.P4(HSIO103NB0-DDR_N_0)
N38037415: TP188.1(TP) U1.U4(HSIO104PB0/CLKIN_N_2/CCC_NW_CLK)
N38037417: TP187.1(TP) U1.T5(HSIO104NB0-DDR_N_0)
N38037425: TP189.1(TP) U1.R2(HSIO105PB0/DQS/CCC_NW_PLL1_OUT0)
N38037427: TP191.1(TP) U1.R1(HSIO105NB0/DQS-DDR_N_0)
N38037459: TP190.1(TP) U1.P2(HSIO106PB0/CCC_NW_CLKIN_N_1-DDR)
N38037461: TP193.1(TP) U1.P1(HSIO106NB0-DDR_N_0)
N38037463: TP194.1(TP) U1.T3(HSIO107PB0/CCC_NW_CLKIN_N_0-DDR)
N38037477: TP192.1(TP) U1.T4(HSIO107NB0-DDR_N_0)
N38037701: TP195.1(TP) U1.V8(HSIO78PB0/CLKIN_N_5-DDR_N_4)
N38037703: TP196.1(TP) U1.U8(HSIO78NB0-DDR_N_4)
N38037705: TP198.1(TP) U1.W6(HSIO79PB0-DDR_N_4)
N38037707: TP199.1(TP) U1.V6(HSIO79NB0-DDR_N_4)
N38037733: TP201.1(TP) U1.U9(HSIO80PB0/CLKIN_N_4-DDR_N_4)
N38037735: TP197.1(TP) U1.R9(HSIO80NB0-DDR_N_4)
N38037737: TP200.1(TP) U1.U7(HSIO81PB0/DQS-DDR_N_4)
N38037751: TP202.1(TP) U1.V7(HSIO81NB0/DQS-DDR_N_4)
N38037753: TP203.1(TP) U1.U5(HSIO82PB0-DDR_N_4)
N38037755: TP204.1(TP) U1.V5(HSIO82NB0-DDR_N_4)
N38037769: TP205.1(TP) U1.P5(HSIO83PB0-DDR_N_4)
N38037771: TP206.1(TP) U1.N7(HSIO83NB0-DDR_N_4)
N38037965: TP209.1(TP) U1.AA3(HSIO90PB0-DDR_N_2)
N38037967: TP208.1(TP) U1.Y2(HSIO90NB0-DDR_N_2)
N38037969: TP211.1(TP) U1.Y1(HSIO91PB0-DDR_N_2)
N38037971: TP210.1(TP) U1.AA2(HSIO91NB0-DDR_N_2)
N38037991: TP213.1(TP) U1.Y4(HSIO92PB0-DDR_N_2)
N38037993: TP207.1(TP) U1.Y5(HSIO92NB0-DDR_N_2)
N38037995: TP212.1(TP) U1.W2(HSIO93PB0/DQS-DDR_N_2)
N38038009: TP214.1(TP) U1.W1(HSIO93NB0/DQS-DDR_N_2)
N38038011: TP215.1(TP) U1.U2(HSIO94PB0-DDR_N_2)
N38038013: TP216.1(TP) U1.V1(HSIO94NB0-DDR_N_2)
N38038021: TP217.1(TP) U1.AA4(HSIO95PB0-DDR_N_2)
N38038023: TP218.1(TP) U1.AA5(HSIO95NB0-DDR_N_2)

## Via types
v1: diameter 0.279, hole 0.152, TOP to BOTTOM, 200 vias

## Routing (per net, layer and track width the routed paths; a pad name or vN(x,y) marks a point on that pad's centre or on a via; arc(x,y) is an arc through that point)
GND: length 20.2
  TOP w0.178: U1.P17 v1(11.49,10.61) ; U1.R8 v1(10.99,15.11) ; U1.N9 v1(11.99,14.61) ; U1.AA6 v1(7.88,15.87) ; U1.N21 v1(12.48,8.61) ; U1.T1 v1(10.74,18.72) ; U1.W20 v1(9.48,9.11) ; U1.J15 v1(14.48,11.61) ; U1.E21 v1(16.48,8.61) ; U1.F1 v1(15.74,18.72) ; U1.L11 v1(12.99,13.61) ; U1.M18 v1(12.98,10.11) ; U1.J9 v1(14.48,14.61) ; U1.J13 v1(14.48,12.12) ; U1.AA11 v1(7.88,13.37) ; U1.L1 v1(13.24,18.72) ; U1.W21 v1(9.48,8.61) ; U1.N4 v1(11.99,16.62) ; U1.A6 v1(18.59,15.87) ; U1.L13 v1(12.99,12.12) ; U1.C21 v1(17.48,8.61) ; U1.L9 v1(12.99,14.61) ; U1.D4 v1(16.49,16.62) ; U1.H7 v1(14.98,15.61) ; U1.K18 v1(13.98,10.11) ; U1.N15 v1(12.48,11.61) ; U1.J11 v1(14.48,13.61) ; U1.R21 v1(11.48,8.61) ; U1.D9 v1(16.49,14.12) ; U1.U21 v1(10.48,8.61) ; U1.H18 v1(14.98,10.11) ; U1.N13 v1(11.99,12.12) ; U1.V4 v1(9.98,16.62) ; U1.K12 v1(13.98,12.62) ; U1.L21 v1(13.48,8.61) ; U1.M12 v1(12.49,12.62) ; U1.J4 v1(13.99,16.62) ; U1.C20 v1(17.48,9.11) ; U1.P18 v1(11.98,10.11) ; U1.G21 v1(15.48,8.61) ; U1.AA21 v1(7.88,8.37) ; U1.G14 v1(15.48,12.11) ; U1.N11 v1(11.99,13.61) ; U1.K10 v1(13.98,14.11) ; U1.AA16 v1(7.88,10.87) ; U1.M10 v1(12.49,14.11) ; U1.AA1 v1(7.88,18.37) ; U1.J21 v1(14.48,8.61) ; U1.A16 v1(18.59,10.87) ; U1.V14 v1(9.98,12.11) ; U1.D14 v1(16.49,11.62) ; U1.H17 v1(14.98,10.61) ; U1.T19 v1(10.98,9.12) ; U1.V9 v1(9.99,14.62) ; U1.A11 v1(18.59,13.37) ; U1.L15 v1(13.48,11.61) ; U1.A1 v1(18.59,18.37) ; U1.A21 v1(18.59,8.37)
VDD: length 4.5
  TOP w0.178: U1.J12 v1(14.48,12.62) ; U1.M15 v1(12.49,11.12) ; U1.K11 v1(13.98,13.61) ; U1.M13 v1(12.49,12.12) ; U1.M11 v1(12.49,13.61) ; U1.N10 v1(11.99,14.11) ; U1.L10 v1(12.99,14.11) ; U1.K13 v1(13.98,12.12) ; U1.K15 v1(13.49,11.12) ; U1.L12 v1(12.99,12.62) ; U1.H15 v1(14.98,11.12) ; U1.K9 v1(13.98,14.61) ; U1.N12 v1(11.99,12.62)
VDD18: length 1.4
  TOP w0.178: U1.R14 v1(10.99,11.62) ; U1.P15 v1(11.98,11.12) ; U1.R10 v1(10.89,13.87) ; U1.P7 v1(11.49,15.61)
VDD25: length 1.7
  TOP w0.178: U1.G15 v1(15.58,11.37) ; U1.M9 v1(12.49,14.61) ; U1.R15 v1(10.99,11.12) ; U1.R7 v1(10.99,15.61) ; U1.G7 v1(15.48,15.12)
VDD_XCVR_CLK: length 0.7
  TOP w0.178: U1.M17 v1(12.49,10.61) ; U1.K17 v1(13.49,10.61)
VDDA: length 1.7
  TOP w0.178: U1.J20 v1(14.48,9.11) ; U1.N20 v1(12.48,9.11) ; U1.R20 v1(11.48,9.11) ; U1.G20 v1(15.48,9.11) ; U1.U20 v1(10.48,9.11)
VDDA25: length 0.7
  TOP w0.178: U1.L19 v1(12.89,9.37) ; U1.L20 v1(13.48,9.11)
VDDAUX2: length 1.4
  TOP w0.178: U1.F17 v1(15.98,10.61) ; U1.G8 v1(14.89,14.87) ; U1.G13 v1(14.89,12.37) ; U1.E6 v1(15.99,15.62)
VDDAUX4: length 0.7
  TOP w0.178: U1.J7 v1(14.48,15.12) ; U1.M7 v1(12.98,15.12)
VDDI0: length 1.7
  TOP w0.178: U1.R5 v1(11.48,16.12) ; U1.V2 v1(9.98,17.62) ; U1.U6 v1(10.48,15.62) ; U1.N2 v1(12.48,17.62) ; U1.Y3 v1(8.98,17.12)
VDDI1: length 2.1
  TOP w0.178: U1.U16 v1(10.48,10.62) ; U1.U11 v1(10.48,13.12) ; U1.Y13 v1(8.98,12.12) ; U1.Y8 v1(8.98,14.62) ; U1.R12 v1(11.48,12.62) ; U1.Y18 v1(8.98,10.11)
VDDI2: length 2.1
  TOP w0.178: U1.E16 v1(15.99,11.11) ; U1.B8 v1(17.49,14.62) ; U1.B18 v1(17.49,10.11) ; U1.B13 v1(17.49,12.61) ; U1.B3 v1(17.49,17.12) ; U1.E11 v1(15.99,13.61)
VDDI3: length 0.7
  TOP w0.178: U1.J10 v1(14.48,14.11) ; U1.G11 v1(14.89,13.37)
VDDI4: length 1.4
  TOP w0.178: U1.G5 v1(15.48,16.61) ; U1.H2 v1(14.98,17.62) ; U1.L5 v1(13.48,16.12) ; U1.D2 v1(16.49,17.62)
XCVR_VREF: length 0.7
  TOP w0.178: U1.E20 v1(16.48,9.11) ; U1.F19 v1(16.08,9.37)
N38004278: length 1.9
  TOP w0.102: 16.76,6.44 16.76,8.35 U1.D21
N38004279: length 2.5
  TOP w0.102: 16.99,6.44 16.99,8.62 U1.D20
N38004284: length 1.9
  TOP w0.102: 15.76,6.44 15.76,8.35 U1.F21
N38004285: length 2.5
  TOP w0.102: U1.F20 15.99,8.62 15.99,6.44
N38032541: length 2.2
  TOP w0.102: U1.M1 12.74,20.55
N38032543: length 2.2
  TOP w0.102: U1.N1 12.24,20.55
N38032613: length 2.8
  TOP w0.102: 12.49,20.55 12.49,18.12 U1.M2
N38032615: length 2.8
  TOP w0.102: 13.5,20.55 13.5,18.61 13.49,18.59 13.49,18.12 U1.L2
N38032633: length 3.4
  TOP w0.102: U1.M4 v1(12.98,17.11)
  BOTTOM w0.102: 12.93,19.91 12.93,18.53 13.21,18.24 13.21,17.35 v1(12.98,17.11)
N38032635: length 3.3
  TOP w0.102: U1.L3 12.99,17.62 12.99,18.59 12.97,18.61 12.97,20.55
N38032653: length 4.4
  TOP w0.102: U1.N5 v1(11.99,16.12)
  BOTTOM w0.102: v1(11.99,16.12) 12.37,16.51 12.37,17.25 12.09,17.53 12.09,19.91
N38032655: length 4
  TOP w0.102: U1.M5 v1(12.98,16.61)
  BOTTOM w0.102: v1(12.98,16.61) 12.65,16.94 12.65,17.29 12.85,17.48 12.85,18.01 12.56,18.3 12.56,19.91
N38032673: length 2.8
  TOP w0.102: 13.99,20.55 13.99,18.12 U1.K2
N38032675: length 2.2
  TOP w0.102: U1.K1 13.74,20.55
N38032693: length 2.2
  TOP w0.102: U1.H1 14.74,20.55
N38032695: length 2.2
  TOP w0.102: U1.J1 14.24,20.55
N38032713: length 3.2
  TOP w0.102: U1.L4 v1(13.48,17.11)
  BOTTOM w0.102: v1(13.48,17.11) 13.66,17.29 13.66,19.91
N38032715: length 3.1
  TOP w0.102: U1.K4 v1(13.98,17.11)
  BOTTOM w0.102: v1(13.98,17.11) 13.98,19.91
N38032733: length 3.3
  TOP w0.102: U1.H4 v1(14.98,17.11)
  BOTTOM w0.102: v1(14.98,17.11) 14.64,17.46 14.64,19.91
N38032735: length 2.8
  TOP w0.102: 14.49,20.55 14.49,18.12 U1.J2
N38032753: length 3.9
  TOP w0.102: U1.H5 v1(14.98,16.61)
  BOTTOM w0.102: 14.32,19.91 14.32,17.27 v1(14.98,16.61)
N38032755: length 3.4
  TOP w0.102: U1.G4 v1(15.48,17.11)
  BOTTOM w0.102: v1(15.48,17.11) 15.72,17.36 15.72,18.08 16.07,18.43 16.07,19.91
N38032773: length 4.5
  TOP w0.102: U1.K7 v1(13.98,15.61)
  L3_SIG1 w0.076: 14.41,19.55 14.41,16.55 13.98,16.12 v1(13.98,15.61)
N38032775: length 4.4
  TOP w0.102: U1.L7 v1(12.99,15.61)
  L3_SIG1 w0.076: v1(12.99,15.61) 12.73,15.87 12.73,19.55
N38032793: length 2.8
  TOP w0.102: 14.99,20.55 14.99,18.12 U1.G2
N38032795: length 2.2
  TOP w0.102: U1.G1 15.24,20.55
N38032813: length 4.5
  TOP w0.102: U1.F4 16.21,17.34 16.7,17.34 16.99,17.63 16.99,20.55
N38032815: length 3.3
  TOP w0.102: 16,20.55 16,18.61 15.99,18.59 15.99,17.62 U1.F3
N38032833: length 3.9
  TOP w0.102: U1.J5 14.48,16.12 v1(14.48,16.11)
  L3_SIG1 w0.076: 14.73,19.55 14.73,16.36 v1(14.48,16.11)
N38032835: length 3.4
  TOP w0.102: U1.K5 v1(13.49,16.61)
  L3_SIG1 w0.076: 13.73,19.55 13.73,16.85 v1(13.49,16.61)
N38032879: length 2.2
  TOP w0.102: U1.B1 17.74,20.55
N38032881: length 2.2
  TOP w0.102: U1.C1 17.24,20.55
N38032909: length 2.8
  TOP w0.102: 17.49,20.55 17.49,18.12 U1.C2
N38032911: length 2.8
  TOP w0.102: 17.99,20.55 17.99,18.12 U1.B2
N38032919: length 3.8
  TOP w0.102: U1.E5 v1(16.48,16.12)
  L3_SIG1 w0.076: 19.81,16.37 16.72,16.37 v1(16.48,16.12)
N38032935: length 4
  TOP w0.102: U1.D5 v1(16.98,16.61)
  BOTTOM w0.102: 20.46,17.03 18.07,17.03 17.66,16.61 v1(16.98,16.61)
N38033008: length 2.8
  TOP w0.102: 15.47,20.55 15.47,18.61 15.49,18.59 15.49,18.12 U1.F2
N38033016: length 2.8
  TOP w0.102: 16.49,20.55 16.49,18.12 U1.E2
N38033024: length 2.2
  TOP w0.102: U1.E1 16.24,20.55
N38033026: length 2.2
  TOP w0.102: U1.D1 16.74,20.55
N38033040: length 3.8
  TOP w0.102: U1.F5 v1(15.98,16.61)
  BOTTOM w0.102: 16.41,19.91 16.41,18.27 15.98,17.84 v1(15.98,16.61)
N38033048: length 5.6
  TOP w0.102: 21.57,17.62 17.44,17.62 16.95,17.12 16.49,17.12 U1.E4
N38033820: length 3.9
  TOP w0.102: U1.D11 v1(16.98,13.61)
  BOTTOM w0.102: v1(16.98,13.61) 18.17,13.61 18.27,13.71 20.46,13.71
N38033822: length 4
  TOP w0.102: U1.D12 v1(16.98,13.11)
  BOTTOM w0.102: 20.46,12.96 18.47,12.96 18.13,13.29 17.16,13.29 v1(16.98,13.11)
N38033842: length 3.9
  TOP w0.102: 21.57,13.1 18.48,13.1 18.46,13.12 17.99,13.12 U1.B11
N38033844: length 4.4
  TOP w0.102: 21.57,13.63 18.48,13.63 18.46,13.62 17.49,13.62 U1.C11
N38033852: length 4.7
  TOP w0.102: U1.E12 v1(16.48,13.11)
  BOTTOM w0.102: v1(16.48,13.11) 16.8,12.8 17.16,12.8 17.32,12.95 18.01,12.95 18.4,12.56 20.46,12.56
N38033854: length 4.9
  TOP w0.102: U1.G12 v1(15.48,12.62)
  L3_SIG1 w0.076: 19.81,12.14 17.32,12.14 17.09,12.37 15.74,12.37 v1(15.48,12.62)
N38033868: length 3.9
  TOP w0.102: 21.57,12.62 17.99,12.62 U1.B12
N38033870: length 3.3
  TOP w0.102: U1.A12 21.57,12.87
N38033896: length 4.9
  TOP w0.102: 21.57,12.12 16.99,12.12 U1.D13
N38033898: length 4.5
  TOP w0.102: U1.E13 v1(16.48,12.61)
  BOTTOM w0.102: v1(16.48,12.61) 16.65,12.44 17.11,12.44 17.34,12.21 20.46,12.21
N38033906: length 3.3
  TOP w0.102: U1.A14 21.57,11.87
N38033908: length 3.3
  TOP w0.102: U1.A13 21.57,12.37
N38033916: length 3.8
  TOP w0.102: U1.E15 v1(16.48,11.12)
  L3_SIG1 w0.076: 19.81,11.36 16.72,11.36 v1(16.48,11.12)
N38033918: length 4.4
  TOP w0.102: U1.E14 v1(16.48,12.11)
  BOTTOM w0.102: 20.46,11.89 17.24,11.89 17.02,12.11 v1(16.48,12.11)
N38033932: length 3.3
  TOP w0.102: U1.A15 21.57,11.37
N38033934: length 3.9
  TOP w0.102: 21.57,11.62 17.99,11.62 U1.B14
N38033960: length 4
  TOP w0.102: U1.D17 v1(16.98,10.61)
  BOTTOM w0.102: 20.46,10.17 18.13,10.17 17.81,10.48 17.11,10.48 v1(16.98,10.61)
N38033962: length 4.1
  TOP w0.102: U1.D16 v1(16.98,11.11)
  BOTTOM w0.102: 20.46,10.43 18.38,10.43 18.08,10.73 17.37,10.73 v1(16.98,11.11)
N38033970: length 3.9
  TOP w0.102: U1.B15 17.99,11.12 18.46,11.12 18.48,11.13 21.57,11.13
N38033972: length 3.9
  TOP w0.102: 21.57,10.6 18.48,10.6 18.46,10.62 17.99,10.62 U1.B16
N38033980: length 3.9
  TOP w0.102: U1.B17 17.99,10.12 21.57,10.12
N38033982: length 3.3
  TOP w0.102: U1.A17 21.57,10.37
N38033996: length 3.4
  TOP w0.102: U1.C16 v1(17.48,11.11)
  BOTTOM w0.102: v1(17.48,11.11) 18.08,11.11 18.21,11.25 20.46,11.25
N38033998: length 3.8
  TOP w0.102: U1.D15 v1(16.98,11.61)
  BOTTOM w0.102: v1(16.98,11.61) 20.46,11.61
N38034024: length 3.8
  TOP w0.102: U1.F18 v1(15.98,10.11)
  BOTTOM w0.102: 16.93,7.08 16.93,9.16 v1(15.98,10.11)
N38034026: length 4.6
  TOP w0.102: U1.E18 v1(16.48,10.11)
  BOTTOM w0.102: v1(16.48,10.11) 17.18,9.41 20.46,9.41
N38034392: length 4.9
  TOP w0.102: U1.D18 16.99,9.62 21.57,9.62
N38034394: length 4.7
  TOP w0.102: U1.E17 v1(16.48,10.61)
  BOTTOM w0.102: 20.46,9.73 17.37,9.73 v1(16.48,10.61)
N38034396: length 3.3
  TOP w0.102: U1.A19 21.57,9.37
N38034398: length 3.3
  TOP w0.102: U1.A18 21.57,9.87
N38034406: length 3
  TOP w0.102: U1.G18 v1(15.48,9.62)
  BOTTOM w0.102: v1(15.48,9.62) 15.79,9.32 15.79,7.08
N38034408: length 4.8
  TOP w0.102: U1.G17 v1(15.48,10.12)
  L3_SIG1 w0.076: v1(15.48,10.12) 15.87,9.73 19.78,9.73
N38034440: length 3.9
  TOP w0.102: 21.57,9.12 17.99,9.12 U1.B19
N38034442: length 3.3
  TOP w0.102: U1.A20 21.57,8.87
N38034456: length 2.6
  TOP w0.102: U1.B20 17.99,8.62 17.99,6.35
N38034458: length 1.9
  TOP w0.102: U1.B21 17.74,6.43
N38034460: length 4.1
  TOP w0.102: U1.D7 v1(16.98,15.61)
  BOTTOM w0.102: 20.46,16.18 18.49,16.18 17.92,15.61 v1(16.98,15.61)
N38034462: length 3.8
  TOP w0.102: U1.E7 v1(16.48,15.61)
  L3_SIG1 w0.076: 19.81,15.36 16.73,15.36 v1(16.48,15.61)
N38034470: length 3.3
  TOP w0.102: U1.A3 21.57,17.37
N38034472: length 3.3
  TOP w0.102: U1.A2 21.57,17.87
N38034504: length 3.3
  TOP w0.102: U1.A4 21.57,16.87
N38034506: length 3.9
  TOP w0.102: 21.57,17.12 17.99,17.12 U1.B4
N38034582: length 4
  TOP w0.102: U1.D6 v1(16.98,16.11)
  BOTTOM w0.102: v1(16.98,16.11) 17.71,16.11 18.2,16.61 20.46,16.61
N38034584: length 4.4
  TOP w0.102: 21.57,16.13 18.48,16.13 18.46,16.12 17.49,16.12 U1.C6
N38034604: length 3.3
  TOP w0.102: U1.A5 21.57,16.37
N38034606: length 3.9
  TOP w0.102: 21.57,16.62 17.99,16.62 U1.B5
N38034614: length 3.9
  TOP w0.102: 21.57,15.12 17.99,15.12 U1.B7
N38034616: length 3.9
  TOP w0.102: 21.57,15.6 18.48,15.6 18.46,15.62 17.99,15.62 U1.B6
N38034678: length 2.5
  TOP w0.102: 13.99,6.44 13.99,8.62 U1.K20
N38034680: length 1.9
  TOP w0.102: U1.K21 13.76,8.35 13.76,6.44
N38034762: length 1.9
  TOP w0.102: 12.76,6.44 12.76,8.35 U1.M21
N38034764: length 2.5
  TOP w0.102: U1.M20 12.99,8.62 12.99,6.44
N38034852: length 2.5
  TOP w0.102: 9.99,6.44 9.99,8.62 U1.V20
N38034854: length 1.9
  TOP w0.102: 9.76,6.44 9.76,8.35 U1.V21
N38034884: length 3.2
  TOP w0.102: U1.L18 v1(13.48,9.62)
  BOTTOM w0.102: v1(13.48,9.62) 13.66,9.62 13.87,9.41 13.87,7.04
N38034886: length 3.7
  TOP w0.102: U1.L17 v1(13.48,10.12)
  BOTTOM w0.102: 14.1,7.04 14.1,9.5 v1(13.48,10.12)
N38034916: length 3.2
  TOP w0.102: U1.N18 v1(12.48,9.62)
  BOTTOM w0.102: 12.09,7.04 12.09,9.41 12.3,9.62 v1(12.48,9.62)
N38034918: length 3.7
  TOP w0.102: U1.N17 v1(12.48,10.12)
  BOTTOM w0.102: v1(12.48,10.12) 11.86,9.5 11.86,7.04
N38034948: length 3.2
  TOP w0.102: U1.J18 v1(14.48,9.62)
  BOTTOM w0.102: 14.87,7.04 14.87,9.41 14.66,9.62 v1(14.48,9.62)
N38034950: length 3.7
  TOP w0.102: U1.J17 v1(14.48,10.12)
  BOTTOM w0.102: v1(14.48,10.12) 15.1,9.5 15.1,7.04
N38034992: length 1.9
  TOP w0.102: U1.H21 14.76,8.35 14.76,6.44
N38034994: length 2.5
  TOP w0.102: U1.H20 14.99,8.62 14.99,6.44
N38035012: length 1.9
  TOP w0.102: 11.76,6.44 11.76,8.35 U1.P21
N38035014: length 2.5
  TOP w0.102: U1.P20 11.99,8.62 11.99,6.44
N38035032: length 2.5
  TOP w0.102: U1.T20 10.99,8.62 10.99,6.44
N38035034: length 1.9
  TOP w0.102: U1.T21 10.76,8.35 10.76,6.44
N38035064: length 3.3
  TOP w0.102: U1.A9 21.57,14.37
N38035090: length 3.9
  TOP w0.102: 21.57,14.62 17.99,14.62 U1.B9
N38035106: length 3.3
  TOP w0.102: U1.A10 21.57,13.87
N38035116: length 4.8
  TOP w0.102: U1.G9 v1(15.48,14.61)
  L3_SIG1 w0.076: 19.81,14.94 17.4,14.94 17.32,14.86 15.73,14.86 v1(15.48,14.61)
N38035126: length 3.9
  TOP w0.102: U1.B10 17.99,14.12 21.57,14.12
N38035136: length 3.3
  TOP w0.102: U1.A8 21.57,14.87
N38035146: length 3.3
  TOP w0.102: U1.A7 21.57,15.37
N38035185: length 3.8
  TOP w0.102: U1.E10 v1(16.48,13.62)
  L3_SIG1 w0.076: 19.81,13.87 16.73,13.87 v1(16.48,13.62)
N38035201: length 3.9
  TOP w0.102: U1.D10 v1(16.98,14.11)
  BOTTOM w0.102: 20.46,14 17.1,14 v1(16.98,14.11)
N38035211: length 4.4
  TOP w0.102: U1.E9 v1(16.48,14.61)
  BOTTOM w0.102: v1(16.48,14.61) 16.65,14.45 17.2,14.45 17.35,14.3 20.44,14.3
N38035221: length 4.5
  TOP w0.102: U1.E8 v1(16.48,15.11)
  BOTTOM w0.102: 20.45,14.96 17.37,14.96 17.18,14.78 16.82,14.78 v1(16.48,15.11)
N38035231: length 3.9
  TOP w0.102: U1.D8 v1(16.98,15.11)
  BOTTOM w0.102: 20.46,15.27 17.14,15.27 v1(16.98,15.11)
N38035241: length 4.8
  TOP w0.102: U1.G10 v1(15.48,14.11)
  L3_SIG1 w0.076: 19.81,14.36 15.73,14.36 v1(15.48,14.11)
N38035401: length 2.8
  TOP w0.102: U1.AA14 5.45,11.87
N38035403: length 2.8
  TOP w0.102: U1.AA13 5.45,12.37
N38035423: length 3.8
  TOP w0.102: U1.V13 v1(9.49,12.12)
  BOTTOM w0.102: 6.21,11.79 9.15,11.79 v1(9.49,12.12)
N38035425: length 3.4
  TOP w0.102: U1.Y14 8.49,12.12 5.45,12.12
N38035433: length 3.7
  TOP w0.102: U1.U13 v1(9.99,12.61)
  L3_SIG1 w0.076: v1(9.99,12.61) 9.65,12.95 6.76,12.95
N38035435: length 4.6
  TOP w0.102: U1.R13 v1(10.99,12.12)
  L3_SIG1 w0.076: 6.92,11.65 10,11.65 10.47,12.12 v1(10.99,12.12)
N38035449: length 3.4
  TOP w0.102: U1.Y12 8.49,12.62 5.45,12.62
N38035451: length 2.8
  TOP w0.102: U1.AA12 5.45,12.87
N38035477: length 3.4
  TOP w0.102: U1.Y11 8.49,13.62 8.01,13.62 7.99,13.63 5.45,13.63
N38035479: length 3.9
  TOP w0.102: U1.W11 8.99,13.12 8.01,13.12 7.99,13.1 5.45,13.1
N38035487: length 4.3
  TOP w0.102: U1.U12 v1(9.99,13.11)
  BOTTOM w0.102: v1(9.99,13.11) 9.8,12.92 8.56,12.92 8.29,12.65 6.21,12.65
N38035489: length 4.8
  TOP w0.102: U1.R11 v1(10.99,13.12)
  L3_SIG1 w0.076: v1(10.99,13.12) 10.74,13.38 8.59,13.38 8.25,13.72 6.76,13.72
N38035497: length 2.8
  TOP w0.102: U1.AA10 5.45,13.87
N38035499: length 3.4
  TOP w0.102: U1.Y10 8.49,14.12 5.45,14.12
N38035513: length 2.8
  TOP w0.102: U1.AA9 5.45,14.37
N38035515: length 3.4
  TOP w0.102: 5.45,14.62 8.49,14.62 U1.Y9
N38035541: length 3.7
  TOP w0.102: U1.V11 v1(9.47,13.63)
  BOTTOM w0.102: v1(9.47,13.63) 8.29,13.63 8.13,13.78 6.21,13.78
N38035543: length 3.8
  TOP w0.102: U1.V12 v1(9.49,12.62)
  BOTTOM w0.102: 6.21,12.24 8.44,12.24 8.82,12.62 v1(9.49,12.62)
N38035551: length 2.8
  TOP w0.102: U1.AA8 5.45,14.87
N38035553: length 3.4
  TOP w0.102: 5.45,15.12 8.49,15.12 U1.Y7
N38035561: length 2.8
  TOP w0.102: U1.AA7 5.45,15.37
N38035563: length 3.4
  TOP w0.102: 5.45,15.6 7.99,15.6 8.01,15.62 8.49,15.62 U1.Y6
N38035577: length 3.7
  TOP w0.102: U1.V10 v1(9.49,14.11)
  BOTTOM w0.102: 6.21,14.04 9.42,14.04 v1(9.49,14.11)
N38035579: length 4.4
  TOP w0.102: U1.U10 v1(9.99,13.62)
  BOTTOM w0.102: 6.21,13.01 8.05,13.01 8.31,13.27 9.64,13.27 v1(9.99,13.62)
N38036549: length 2.8
  TOP w0.102: U1.AA20 5.45,8.87
N38036551: length 2
  TOP w0.102: U1.Y21 8.74,6.37
N38036553: length 2.6
  TOP w0.102: 8.49,6.37 8.49,8.62 U1.Y20
N38036573: length 3.4
  TOP w0.102: 5.45,9.12 8.49,9.12 U1.Y19
N38036575: length 3.8
  TOP w0.102: U1.V18 8.99,9.12 8.99,6.37
N38036577: length 3.1
  TOP w0.102: U1.U18 v1(9.99,9.62)
  BOTTOM w0.102: v1(9.99,9.62) 9.77,9.4 9.77,6.99
N38036585: length 3.3
  TOP w0.102: U1.R17 v1(11.48,10.12)
  L3_SIG1 w0.076: 12,7.4 12,9.61 v1(11.48,10.12)
N38036587: length 2.7
  TOP w0.102: U1.R18 v1(10.99,9.62)
  L3_SIG1 w0.076: v1(10.99,9.62) 11.23,9.38 11.23,7.4
N38036619: length 5.2
  TOP w0.102: U1.T17 v1(10.49,10.12)
  BOTTOM w0.102: 6.21,9.42 8.77,9.42 9.8,10.44 10.17,10.44 v1(10.49,10.12)
N38036621: length 3.1
  TOP w0.102: U1.T18 v1(10.49,9.62)
  BOTTOM w0.102: 10.15,6.99 10.15,9.28 v1(10.49,9.62)
N38036623: length 3.8
  TOP w0.102: U1.U17 v1(9.99,10.12)
  BOTTOM w0.102: v1(9.99,10.12) 9.15,9.28 9.15,6.99
N38036637: length 4.6
  TOP w0.102: 5.45,9.62 8.99,9.62 U1.V17
N38036639: length 2.8
  TOP w0.102: U1.AA19 5.45,9.37
N38036641: length 2.8
  TOP w0.102: U1.AA18 5.45,9.87
N38036649: length 3.7
  TOP w0.102: U1.V15 v1(9.49,11.12)
  BOTTOM w0.102: v1(9.49,11.12) 8.98,11.12 8.91,11.19 6.21,11.19
N38036651: length 3.9
  TOP w0.102: U1.V16 9.32,10.45 v1(9.32,10.44)
  BOTTOM w0.102: v1(9.32,10.44) 8.81,10.44 8.47,10.1 6.21,10.1
N38036683: length 2.8
  TOP w0.102: U1.AA17 5.45,10.37
N38036685: length 3.4
  TOP w0.102: 5.45,10.12 8.49,10.12 U1.Y17
N38036687: length 4.7
  TOP w0.102: U1.U14 10.48,11.62 v1(10.48,11.62)
  BOTTOM w0.102: v1(10.48,11.62) 9.57,11.62 9.45,11.51 6.21,11.51
N38036701: length 4.4
  TOP w0.102: U1.U15 v1(9.99,11.12)
  BOTTOM w0.102: v1(9.99,11.12) 9.64,10.77 8.67,10.77 8.38,10.48 6.21,10.48
N38036703: length 3.4
  TOP w0.102: U1.Y16 8.49,11.12 8.01,11.12 7.99,11.13 5.45,11.13
N38036705: length 3.9
  TOP w0.102: 5.45,10.6 7.99,10.6 8.01,10.62 8.99,10.62 U1.W16
N38036713: length 2.8
  TOP w0.102: U1.AA15 5.45,11.37
N38036715: length 3.4
  TOP w0.102: U1.Y15 8.49,11.62 5.45,11.62
N38037389: length 2.2
  TOP w0.102: U1.U1 10.24,20.55
N38037391: length 2.8
  TOP w0.102: 10.47,20.55 10.47,18.61 10.49,18.59 10.49,18.12 U1.T2
N38037393: length 3.2
  TOP w0.102: U1.R4 v1(11.48,17.11)
  BOTTOM w0.102: 11.31,19.91 11.31,17.29 v1(11.48,17.11)
N38037413: length 3.3
  TOP w0.102: U1.P4 v1(11.98,17.11)
  BOTTOM w0.102: v1(11.98,17.11) 11.7,17.4 11.7,19.91
N38037415: length 5.1
  TOP w0.102: 5.47,17.62 9.02,17.62 9.52,17.12 9.98,17.12 U1.U4
N38037417: length 4
  TOP w0.102: U1.T5 v1(10.98,16.61)
  BOTTOM w0.102: 10.05,19.91 10.05,18.21 10.46,17.8 10.46,17.13 v1(10.98,16.61)
N38037425: length 2.8
  TOP w0.102: 11.49,20.55 11.49,18.12 U1.R2
N38037427: length 2.2
  TOP w0.102: U1.R1 11.24,20.55
N38037459: length 2.8
  TOP w0.102: U1.P2 11.99,18.12 11.99,20.55
N38037461: length 2.2
  TOP w0.102: U1.P1 11.74,20.55
N38037463: length 3.3
  TOP w0.102: U1.T3 10.99,17.62 10.99,18.59 11,18.61 11,20.55
N38037477: length 4.5
  TOP w0.102: 9.49,20.55 9.49,17.64 9.78,17.35 10.25,17.35 U1.T4
N38037701: length 3.7
  TOP w0.102: U1.V8 v1(9.49,14.62)
  BOTTOM w0.102: 6.21,14.35 9.21,14.35 v1(9.49,14.62)
N38037703: length 4.2
  TOP w0.102: U1.U8 v1(9.99,15.11)
  BOTTOM w0.102: 6.21,14.95 9.83,14.95 v1(9.99,15.11)
N38037705: length 3.9
  TOP w0.102: U1.W6 8.99,16.12 8.01,16.12 7.99,16.13 5.45,16.13
N38037707: length 3.9
  TOP w0.102: U1.V6 v1(9.49,16.11)
  BOTTOM w0.102: v1(9.49,16.11) 8.85,16.11 8.18,16.79 6.21,16.79
N38037733: length 3.7
  TOP w0.102: U1.U9 v1(9.99,14.12)
  L3_SIG1 w0.076: v1(9.99,14.12) 9.75,14.36 6.76,14.36
N38037735: length 4.7
  TOP w0.102: U1.R9 v1(10.99,14.61)
  L3_SIG1 w0.076: v1(10.99,14.61) 10.74,14.86 9.7,14.86 9.56,15 6.76,15
N38037737: length 4.3
  TOP w0.102: U1.U7 v1(9.99,15.61)
  BOTTOM w0.102: 6.21,15.25 9.63,15.25 v1(9.99,15.61)
N38037751: length 3.9
  TOP w0.102: U1.V7 v1(9.49,15.61)
  BOTTOM w0.102: 6.21,16.38 7.96,16.38 8.72,15.61 v1(9.49,15.61)
N38037753: length 4
  TOP w0.102: U1.U5 v1(10.48,16.61)
  BOTTOM w0.102: 9.7,19.91 9.7,17.39 v1(10.48,16.61)
N38037755: length 3.9
  TOP w0.102: U1.V5 v1(9.49,16.61)
  BOTTOM w0.102: 6.21,17.27 8.28,17.27 8.93,16.61 v1(9.49,16.61)
N38037769: length 4.1
  TOP w0.102: U1.P5 v1(11.49,16.61)
  BOTTOM w0.102: 10.41,19.91 10.41,18.5 10.9,18.01 10.9,17.2 v1(11.49,16.61)
N38037771: length 4.5
  TOP w0.102: U1.N7 v1(12.48,15.61)
  L3_SIG1 w0.076: 12.01,19.55 12.01,17.63 12.48,17.15 v1(12.48,15.61)
N38037965: length 2.8
  TOP w0.102: U1.AA3 5.45,17.37
N38037967: length 2.8
  TOP w0.102: 8.49,20.55 8.49,18.12 U1.Y2
N38037969: length 2.2
  TOP w0.102: U1.Y1 8.74,20.55
N38037971: length 2.8
  TOP w0.102: U1.AA2 5.45,17.87
N38037991: length 3.4
  TOP w0.102: 5.45,17.12 8.49,17.12 U1.Y4
N38037993: length 3.4
  TOP w0.102: U1.Y5 8.49,16.62 5.45,16.62
N38037995: length 2.8
  TOP w0.102: 8.99,20.55 8.99,18.12 U1.W2
N38038009: length 2.2
  TOP w0.102: U1.W1 9.24,20.55
N38038011: length 2.8
  TOP w0.102: 9.99,20.55 9.99,18.12 U1.U2
N38038013: length 2.2
  TOP w0.102: U1.V1 9.74,20.55
N38038021: length 2.8
  TOP w0.102: U1.AA4 5.45,16.87
N38038023: length 2.8
  TOP w0.102: U1.AA5 5.45,16.37

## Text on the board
BOTTOM: 06_BOTTOM
Ref Des/Assembly Bottom: ASSEMBLY BOTTOM
Ref Des/Silkscreen Bottom: MAY 2018 | MICROSEMI TECHNICAL SUPPORT | 305-PD-18-0223 | +1(800) 262-1060
User.Comments: CR_1_25 | CR_1_24 | CR_2_16 | CR_1_28 | CR_1_19 | CR_1_27 | CR_1_26 | CR_1_20 | CR_1_23 | CR_2_10 | CR_2_15 | CR_1_10 | CR_1_22 | CR_1_21
TOP: 01_TOP
Ref Des/Assembly Top: ASSEMBLY TOP
